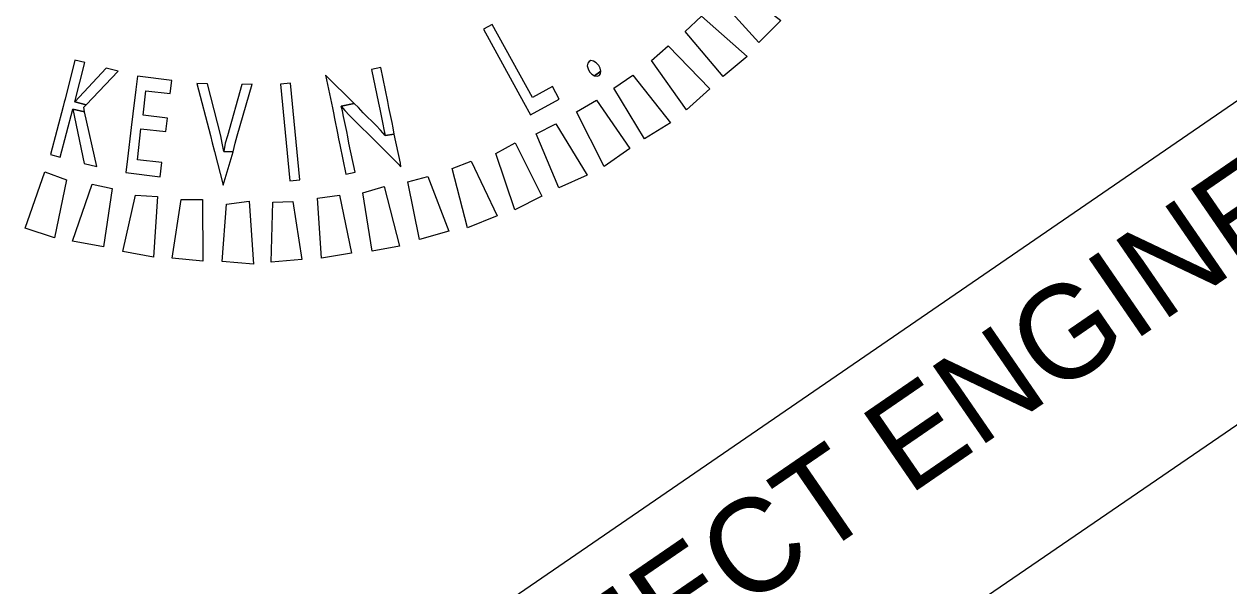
# Model space of a CAD drawing. Extents: x 2385901 to 2398119, y 552503 to 560016.
# Drawn here: x 2397482.5 to 2397537.9, y 559826.4 to 559852.3 of the extents above; entities that cross this region are included whole.
import ezdxf

# ---------------------------------------------------------------- set-up
doc = ezdxf.new("R2010")
doc.units = 0
doc.layers.add('Old_Level_18', color=7, linetype='Continuous')
doc.layers.add('Old_Level_40', color=7, linetype='Continuous')

msp = doc.modelspace()

# ---------------------------------------------------------------- linework, layer by layer
at = {"layer": 'Old_Level_18'}
msp.add_line((2397464.577, 559798.162), (2397574.693, 559873.801), dxfattribs=at)
for points in [[(2397515.065, 559854.166), (2397517.285, 559852.441), (2397516.271, 559851.425), (2397514.447, 559853.463)], [(2397505.473, 559848.677), (2397505.79, 559848.099), (2397507.103, 559848.815), (2397506.795, 559849.4), (2397505.882, 559848.892), (2397504.036, 559852.255), (2397503.627, 559852.04)], [(2397513.648, 559852.635), (2397515.743, 559850.784), (2397514.643, 559849.855), (2397512.896, 559851.933)], [(2397512.114, 559851.276), (2397514.035, 559849.292), (2397512.95, 559848.321), (2397511.344, 559850.601)], [(2397484.333, 559848.485), (2397483.751, 559846.28), (2397484.199, 559846.15), (2397484.774, 559848.364), (2397485.316, 559848.232), (2397485.277, 559848.444), (2397485.385, 559848.557), (2397484.861, 559848.702), (2397485.321, 559850.504), (2397484.861, 559850.613), (2397484.419, 559848.823), (2397484.385, 559848.68)], [(2397508.607, 559849.968), (2397508.735, 559849.897), (2397509.027, 559850.11), (2397508.988, 559850.243), (2397508.926, 559850.373), (2397508.806, 559850.49), (2397508.686, 559850.567), (2397508.565, 559850.589), (2397508.486, 559850.549), (2397508.418, 559850.475), (2397508.395, 559850.353), (2397508.433, 559850.22), (2397508.508, 559850.073)], [(2397486.311, 559850.242), (2397484.861, 559848.702), (2397485.385, 559848.557), (2397486.859, 559850.101)], [(2397499.059, 559847.429), (2397499.123, 559847.141), (2397499.538, 559847.214), (2397499.482, 559847.507), (2397499.433, 559847.753), (2397499.293, 559848.439), (2397499.241, 559848.709), (2397498.925, 559850.27), (2397498.498, 559850.176), (2397498.817, 559848.63), (2397498.87, 559848.361), (2397499.01, 559847.674)], [(2397508.857, 559849.874), (2397508.95, 559849.912), (2397509.01, 559849.98), (2397509.027, 559850.11), (2397508.735, 559849.897)], [(2397487.285, 559846.081), (2397487.206, 559845.443), (2397488.789, 559845.243), (2397488.856, 559845.9), (2397487.747, 559846.027), (2397487.903, 559847.461), (2397489.042, 559847.328), (2397489.119, 559847.951), (2397488.003, 559848.087), (2397488.13, 559849.196), (2397489.248, 559849.076), (2397489.322, 559849.683), (2397487.738, 559849.883), (2397487.671, 559849.266), (2397487.535, 559848.151), (2397487.456, 559847.512)], [(2397491.279, 559846.41), (2397491.677, 559844.865), (2397492.135, 559846.401), (2397491.704, 559846.41), (2397491.634, 559846.8), (2397491.569, 559847.127), (2397490.953, 559849.53), (2397490.468, 559849.542), (2397491.093, 559847.144), (2397491.173, 559846.815)], [(2397491.774, 559846.79), (2397491.704, 559846.41), (2397492.135, 559846.401), (2397492.232, 559846.799), (2397492.325, 559847.128), (2397492.325, 559847.128), (2397493.017, 559849.501), (2397492.543, 559849.495), (2397491.878, 559847.14)], [(2397494.309, 559849.513), (2397494.735, 559845.069), (2397495.199, 559845.109), (2397494.772, 559849.553)], [(2397497.039, 559846.718), (2397497.316, 559845.369), (2397497.733, 559845.456), (2397497.453, 559846.79), (2397497.398, 559847.084), (2397497.358, 559847.335), (2397497.209, 559848.016), (2397497.163, 559848.276), (2397497.102, 559848.5), (2397497.698, 559848.617), (2397496.375, 559849.924), (2397496.693, 559848.418), (2397496.745, 559848.188), (2397496.791, 559847.928), (2397496.925, 559847.25), (2397496.98, 559846.996)], [(2397510.485, 559849.918), (2397512.227, 559847.731), (2397511.03, 559847.001), (2397509.62, 559849.324)], [(2397484.774, 559848.364), (2397485.295, 559845.868), (2397485.882, 559845.728), (2397485.316, 559848.232)], [(2397499.696, 559845.863), (2397499.841, 559845.71), (2397499.817, 559845.88), (2397499.538, 559847.214), (2397499.123, 559847.141), (2397498.901, 559847.387), (2397498.707, 559847.612), (2397498.107, 559848.195), (2397497.892, 559848.432), (2397497.698, 559848.617), (2397497.102, 559848.5), (2397497.269, 559848.296), (2397497.478, 559848.068), (2397498.069, 559847.479), (2397498.29, 559847.272), (2397498.542, 559847.021)], [(2397508.818, 559848.773), (2397510.348, 559846.546), (2397509.173, 559845.726), (2397507.9, 559848.235)], [(2397506.955, 559847.679), (2397508.39, 559845.32), (2397507.096, 559844.75), (2397506.045, 559847.226)], [(2397505.095, 559846.812), (2397506.316, 559844.36), (2397505.066, 559843.727), (2397504.201, 559846.317)], [(2397503.065, 559845.962), (2397504.259, 559843.451), (2397502.893, 559842.91), (2397502.202, 559845.634)], [(2397484.486, 559845.114), (2397483.929, 559842.448), (2397482.588, 559842.894), (2397483.492, 559845.479)], [(2397501.073, 559845.27), (2397502.036, 559842.747), (2397500.701, 559842.373), (2397500.16, 559845.014)], [(2397486.576, 559844.718), (2397486.189, 559842.037), (2397484.765, 559842.293), (2397485.66, 559844.911)], [(2397499.068, 559844.808), (2397499.777, 559842.057), (2397498.515, 559841.827), (2397498.092, 559844.509)], [(2397488.668, 559844.338), (2397488.474, 559841.55), (2397487.068, 559841.818), (2397487.651, 559844.408)], [(2397490.727, 559844.2), (2397490.746, 559841.372), (2397489.339, 559841.507), (2397489.753, 559844.207)], [(2397492.876, 559844.123), (2397493.071, 559841.232), (2397491.632, 559841.357), (2397491.829, 559843.987)], [(2397494.882, 559844.121), (2397495.298, 559841.448), (2397493.877, 559841.334), (2397493.954, 559844.081)], [(2397497.02, 559844.409), (2397497.579, 559841.741), (2397496.189, 559841.503), (2397496.011, 559844.273)]]:
    msp.add_lwpolyline(points, close=True, dxfattribs=at)
at = {"layer": 'Old_Level_40'}
msp.add_line((2397600.937, 559876.856), (2397452.468, 559775.007), dxfattribs=at)

# ---------------------------------------------------------------- texts
at = {"layer": 'Old_Level_18'}
msp.add_text('PROJECT ENGINEER', height=4.30175, rotation=34.4849, dxfattribs=at).set_placement((2397499.708, 559814.465))

doc.saveas('drawing.dxf')
